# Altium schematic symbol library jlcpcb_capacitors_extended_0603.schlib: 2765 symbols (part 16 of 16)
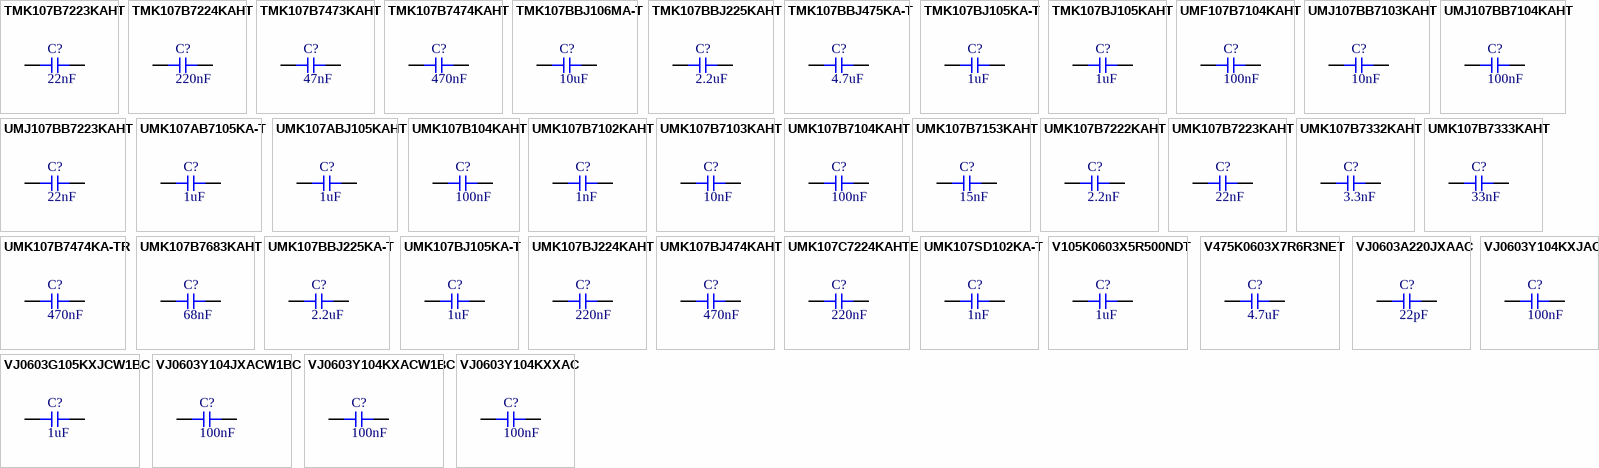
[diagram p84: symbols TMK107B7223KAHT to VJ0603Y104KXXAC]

## UMK107BJ224KAHT
designator C?  Capacitance: 220nF  (hidden comment: *)
Capacitor, Ceramic (MLCC), 220nF, ±10%, 50V, X5R, ±10%, SMD 0603; Manufacturer: Taiyo Yuden; Manufacturer Part Number: UMK107BJ224KAHT
footprint CAP-0603 (0603 (1608M) Capacitor)
pins: 1, 2

## UMK107BJ474KAHT
designator C?  Capacitance: 470nF  (hidden comment: *)
Capacitor, Ceramic (MLCC), 470nF, ±10%, 50V, X5R, ±10%, SMD 0603; Manufacturer: Taiyo Yuden; Manufacturer Part Number: UMK107BJ474KAHT
footprint CAP-0603 (0603 (1608M) Capacitor)
pins: 1, 2

## UMK107C7224KAHTE
designator C?  Capacitance: 220nF  (hidden comment: *)
Capacitor, Ceramic (MLCC), 220nF, ±10%, 50V, X7S, ±10%, SMD 0603; Manufacturer: Taiyo Yuden; Manufacturer Part Number: UMK107C7224KAHTE
footprint CAP-0603 (0603 (1608M) Capacitor)
pins: 1, 2

## UMK107SD102KA-T
designator C?  Capacitance: 1nF  (hidden comment: *)
Capacitor, Ceramic (MLCC), 1nF, ±10%, 50V, ±10%, SMD 0603; Manufacturer: Taiyo Yuden; Manufacturer Part Number: UMK107SD102KA-T
footprint CAP-0603 (0603 (1608M) Capacitor)
pins: 1, 2

## V105K0603X5R500NDT
designator C?  Capacitance: 1uF  (hidden comment: *)
Capacitor, Ceramic (MLCC), 1uF, ±10%, 50V, ±10%, SMD 0603; Manufacturer: VIIYONG; Manufacturer Part Number: V105K0603X5R500NDT
footprint CAP-0603 (0603 (1608M) Capacitor)
pins: 1, 2

## V475K0603X7R6R3NET
designator C?  Capacitance: 4.7uF  (hidden comment: *)
Capacitor, Ceramic (MLCC), 4.7uF, ±10%, 6.3V, X7R, ±10%, SMD 0603; Manufacturer: VIIYONG; Manufacturer Part Number: V475K0603X7R6R3NET
footprint CAP-0603 (0603 (1608M) Capacitor)
pins: 1, 2

## VJ0603A220JXAAC
designator C?  Capacitance: 22pF  (hidden comment: *)
Capacitor, Ceramic (MLCC), 22pF, ±5%, 50V, C0G, ±5%, SMD 0603; Manufacturer: Vishay Intertech; Manufacturer Part Number: VJ0603A220JXAAC
footprint CAP-0603 (0603 (1608M) Capacitor)
pins: 1, 2

## VJ0603G105KXJCW1BC
designator C?  Capacitance: 1uF  (hidden comment: *)
Capacitor, Ceramic (MLCC), 1uF, ±10%, 16V, X5R, ±10%, SMD 0603; Manufacturer: Vishay Intertech; Manufacturer Part Number: VJ0603G105KXJCW1BC
footprint CAP-0603 (0603 (1608M) Capacitor)
pins: 1, 2

## VJ0603Y104JXACW1BC
designator C?  Capacitance: 100nF  (hidden comment: *)
Capacitor, Ceramic (MLCC), 100nF, ±5%, 50V, X7R, ±5%, SMD 0603; Manufacturer: Vishay Intertech; Manufacturer Part Number: VJ0603Y104JXACW1BC
footprint CAP-0603 (0603 (1608M) Capacitor)
pins: 1, 2

## VJ0603Y104KXACW1BC
designator C?  Capacitance: 100nF  (hidden comment: *)
Capacitor, Ceramic (MLCC), 100nF, ±10%, 50V, X7R, ±10%, SMD 0603; Manufacturer: Vishay Intertech; Manufacturer Part Number: VJ0603Y104KXACW1BC
footprint CAP-0603 (0603 (1608M) Capacitor)
pins: 1, 2

## VJ0603Y104KXJAC
designator C?  Capacitance: 100nF  (hidden comment: *)
Capacitor, Ceramic (MLCC), 100nF, ±10%, 16V, X7R, ±10%, SMD 0603; Manufacturer: Vishay Intertech; Manufacturer Part Number: VJ0603Y104KXJAC
footprint CAP-0603 (0603 (1608M) Capacitor)
pins: 1, 2

## VJ0603Y104KXXAC
designator C?  Capacitance: 100nF  (hidden comment: *)
Capacitor, Ceramic (MLCC), 100nF, ±10%, 25V, X7R, ±10%, SMD 0603; Manufacturer: Vishay Intertech; Manufacturer Part Number: VJ0603Y104KXXAC
footprint CAP-0603 (0603 (1608M) Capacitor)
pins: 1, 2

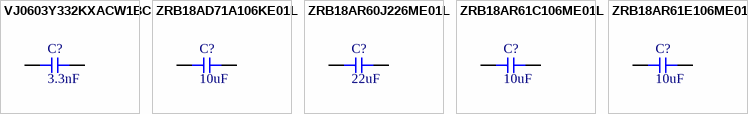
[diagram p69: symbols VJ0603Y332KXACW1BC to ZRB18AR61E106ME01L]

## VJ0603Y332KXACW1BC
designator C?  Capacitance: 3.3nF  (hidden comment: *)
Capacitor, Ceramic (MLCC), 3.3nF, ±10%, 50V, X7R, ±10%, SMD 0603; Manufacturer: Vishay Intertech; Manufacturer Part Number: VJ0603Y332KXACW1BC
footprint CAP-0603 (0603 (1608M) Capacitor)
pins: 1, 2

## ZRB18AD71A106KE01L
designator C?  Capacitance: 10uF  (hidden comment: *)
Capacitor, Ceramic (MLCC), 10uF, ±10%, 10V, X7T, ±10%, SMD 0603; Manufacturer: Murata Electronics; Manufacturer Part Number: ZRB18AD71A106KE01L
footprint CAP-0603 (0603 (1608M) Capacitor)
pins: 1, 2

## ZRB18AR60J226ME01L
designator C?  Capacitance: 22uF  (hidden comment: *)
Capacitor, Ceramic (MLCC), 22uF, ±20%, ±20%, SMD 0603; Manufacturer: Murata Electronics; Manufacturer Part Number: ZRB18AR60J226ME01L
footprint CAP-0603 (0603 (1608M) Capacitor)
pins: 1, 2

## ZRB18AR61C106ME01L
designator C?  Capacitance: 10uF  (hidden comment: *)
Capacitor, Ceramic (MLCC), 10uF, 16V, SMD 0603; Manufacturer: Murata Electronics; Manufacturer Part Number: ZRB18AR61C106ME01L
footprint CAP-0603 (0603 (1608M) Capacitor)
pins: 1, 2

## ZRB18AR61E106ME01L
designator C?  Capacitance: 10uF  (hidden comment: *)
Capacitor, Ceramic (MLCC), 10uF, ±20%, ±20%, SMD 0603; Manufacturer: Murata Electronics; Manufacturer Part Number: ZRB18AR61E106ME01L
footprint CAP-0603 (0603 (1608M) Capacitor)
pins: 1, 2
